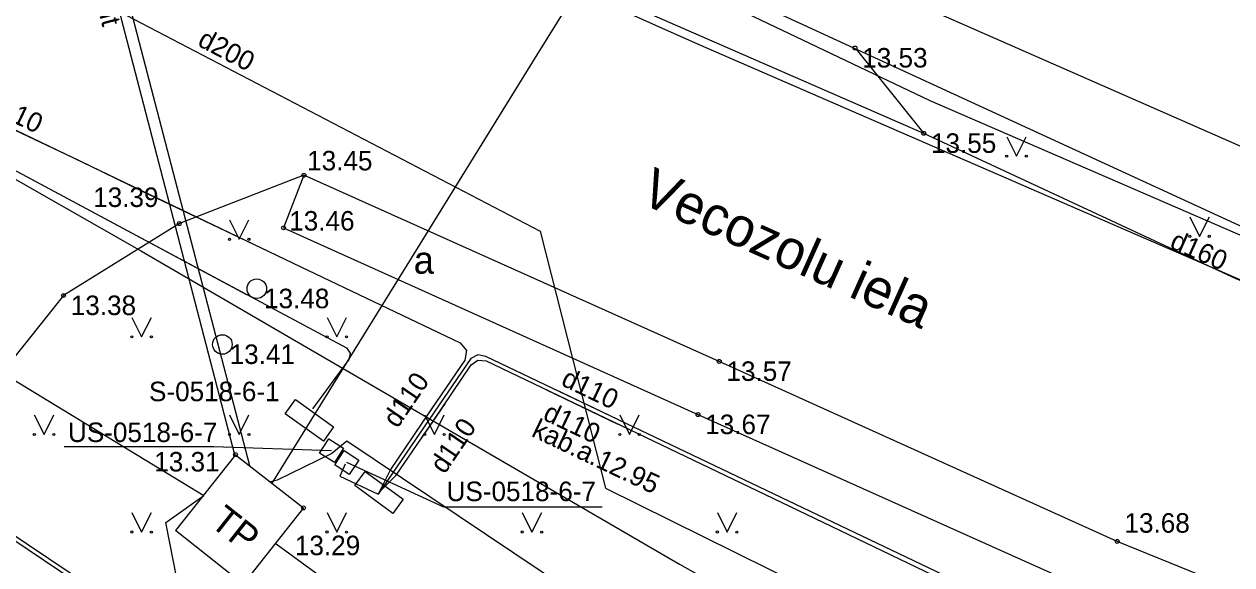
# Model space of a CAD drawing. Extents: x 503904 to 504094, y 304688 to 304960.
# Drawn here: x 503996.99 to 504027.93, y 304884.16 to 304898.01 of the extents above; entities that cross this region are included whole.
import ezdxf

# ---------------------------------------------------------------- set-up
doc = ezdxf.new("R2010")
doc.units = 0
for name, color, linetype in [('APGR_SARK_####_####_#', 7, 'Continuous'), ('APGS_ACRL_####_####_#', 7, 'Continuous'), ('APGS_ACRL_####_TKST_#', 7, 'Continuous'), ('APGS_ELEM_####_####_#', 7, 'Continuous'), ('APGS_VADP_ZSPR_####_#', 7, 'Continuous'), ('APGS_VADP_ZSPR_TKST_#', 7, 'Continuous'), ('BUVE_ELEM_####_####_#', 7, 'Continuous'), ('CELI_CAPM_####_####_#', 7, 'Continuous'), ('CELI_CMAL_####_####_#', 7, 'Continuous'), ('CELI_CSEG_####_TKST_#', 7, 'Continuous'), ('CELI_IELA_####_TKST_#', 7, 'Continuous'), ('CELI_TAKA_####_####_#', 7, 'Continuous'), ('ELEK_ACRL_####_####_#', 7, 'Continuous'), ('ELEK_ELEM_####_####_#', 7, 'Continuous'), ('ELEK_ELEM_####_TKST_#', 7, 'Continuous'), ('ELEK_STTP_####_####_#', 7, 'Continuous'), ('ELEK_STTP_####_TKST_#', 7, 'Continuous'), ('ELEK_VADP_VSPR_####_#', 7, 'Continuous'), ('ELEK_VADP_ZSPR_####_#', 7, 'Continuous'), ('ELEK_VADP_ZSPR_TKST_#', 7, 'Continuous'), ('ELEK_VADV_VSPR_####_#', 7, 'Continuous'), ('ELEK_VADV_ZSPR_####_#', 7, 'Continuous'), ('GAZE_VADP_VSP2_####_#', 7, 'Continuous'), ('GAZE_VADP_VSP2_TKST_#', 7, 'Continuous'), ('RAMI_UZMR_####_####_#', 7, 'Continuous'), ('RELJ_AATZ_####_TKST_#', 7, 'Continuous'), ('RELJ_ELEM_####_####_#', 7, 'Continuous'), ('ROBZ_UZMR_####_####_#', 7, 'Continuous'), ('SAKK_KKAN_####_####_#', 7, 'Continuous'), ('TERT_ELEM_####_####_#', 7, 'Continuous'), ('UDTK_VADP_UDEN_####_#', 7, 'Continuous'), ('UDTK_VADP_UDEN_TKST_#', 7, 'Continuous')]:
    doc.layers.add(name, color=color, linetype=linetype)

msp = doc.modelspace()

# ---------------------------------------------------------------- linework, layer by layer
at = {"layer": 'APGR_SARK_####_####_#'}
msp.add_line((503977.453, 304917.18), (504048.875, 304885.773), dxfattribs=at)
at = {"layer": 'APGS_ACRL_####_####_#'}
for points in [[(503997.708, 304905.8), (503994.46, 304899.393), (503993.378, 304897.257), (503993.361, 304897.025), (503993.516, 304896.851), (503996.758, 304895.298), (503998.379, 304894.525), (504000, 304893.745), (504003.241, 304892.193)], [(504010.375, 304888.642), (504012.204, 304887.766)], [(504012.399, 304887.79), (504010.595, 304888.651)], [(504006.987, 304887.503), (504007.597, 304888.4)], [(504007.766, 304888.284), (504007.156, 304887.387)]]:
    msp.add_lwpolyline(points, dxfattribs=at)
at = {"layer": 'APGS_ELEM_####_####_#'}
msp.add_lwpolyline([(504005.73, 304886.552), (504006.698, 304885.843), (504006.432, 304885.48), (504005.464, 304886.189)], close=True, dxfattribs=at)
at = {"layer": 'APGS_VADP_ZSPR_####_#'}
for points in [[(503994.396, 304908.162), (503998.01, 304906.396), (503995.543, 304901.529), (503993.378, 304897.257), (503993.361, 304897.025), (503993.516, 304896.85), (503996.758, 304895.3), (504000, 304893.749), (504004.081, 304891.797), (504008.162, 304889.845), (504008.322, 304889.653), (504008.281, 304889.406), (504007.328, 304888.005), (504006.375, 304886.604), (504006.058, 304885.968)], [(504034.948, 304837.203), (504032.464, 304838.354), (504032.46, 304838.624), (504032.497, 304838.963), (504034.767, 304843.029), (504037.037, 304847.095), (504041.785, 304855.598), (504046.532, 304864.101), (504046.909, 304866.055), (504048.051, 304868.025), (504049.192, 304869.995), (504049.205, 304870.202), (504049.157, 304870.343), (504042.295, 304873.577), (504035.433, 304876.812), (504031.898, 304878.478), (504020.359, 304883.989), (504008.82, 304889.499), (504008.617, 304889.54), (504008.431, 304889.443), (504006.058, 304885.968)], [(504006.081, 304886.016), (504006.524, 304886.457), (504007.485, 304887.87), (504008.446, 304889.284), (504008.616, 304889.405), (504008.824, 304889.386), (504016.168, 304885.866), (504023.512, 304882.345), (504029.465, 304879.528), (504035.491, 304876.677), (504037.943, 304875.532), (504038.212, 304875.634), (504038.416, 304876.08), (504038.226, 304875.558), (504038.331, 304875.343), (504039.638, 304874.712), (504041.796, 304873.674), (504045.914, 304871.662), (504049.181, 304870.056), (504051.511, 304869.798), (504052.144, 304869.735)], [(504005.217, 304886.74), (504005.076, 304886.431), (504006.058, 304885.968)]]:
    msp.add_lwpolyline(points, dxfattribs=at)
at = {"layer": 'BUVE_ELEM_####_####_#'}
for centre in [(504002.95, 304891.234), (504002.069, 304889.806)]:
    msp.add_circle(centre, 0.25, dxfattribs=at)
at = {"layer": 'CELI_CAPM_####_####_#'}
msp.add_lwpolyline([(504042.469, 304879.012), (504039.999, 304879.481), (504033.709, 304881.219), (504024.994, 304884.76), (504014.798, 304889.372), (504004.157, 304894.141)], dxfattribs=at)
at = {"layer": 'CELI_CMAL_####_####_#'}
for points in [[(504056.369, 304885.722), (504054.86, 304884.787), (504047.246, 304885.659), (504038.184, 304887.536), (504028.058, 304891.478), (504020.037, 304895.213), (504011.327, 304899.02)], [(504004.157, 304894.141), (504000.966, 304892.903), (503997.999, 304891.059), (503994.598, 304886.807), (503991.776, 304882.213), (503990.847, 304877.876)], [(504004.157, 304894.141), (504003.635, 304892.793), (504014.253, 304888.009), (504024.188, 304883.551), (504033.132, 304879.868), (504039.457, 304878.088), (504042.126, 304877.631), (504042.469, 304879.012)]]:
    msp.add_lwpolyline(points, dxfattribs=at)
at = {"layer": 'CELI_TAKA_####_####_#'}
msp.add_lwpolyline([(504018.302, 304897.367), (504020.037, 304895.213)], dxfattribs=at)
at = {"layer": 'ELEK_ACRL_####_####_#'}
msp.add_lwpolyline([(503986.232, 304899.912), (504002.69, 304891.089)], dxfattribs=at)
at = {"layer": 'ELEK_ELEM_####_####_#'}
for points in [[(504003.942, 304888.393), (504004.919, 304887.698), (504004.658, 304887.331), (504003.681, 304888.026)], [(504004.938, 304886.781), (504004.561, 304887.019), (504004.796, 304887.391), (504005.173, 304887.153)], [(504005.317, 304886.477), (504004.946, 304886.725), (504005.191, 304887.091), (504005.562, 304886.843)]]:
    msp.add_lwpolyline(points, close=True, dxfattribs=at)
at = {"layer": 'ELEK_ELEM_####_TKST_#'}
for points in [[(503998.012, 304887.191), (504001.849, 304887.191), (504004.867, 304887.086)], [(504011.796, 304885.637), (504007.738, 304885.637), (504005.254, 304886.784)]]:
    msp.add_lwpolyline(points, dxfattribs=at)
at = {"layer": 'ELEK_STTP_####_####_#'}
for points in [[(504002.404, 304886.982), (504004.147, 304885.62), (504002.601, 304883.668), (504000.867, 304885.041)], [(504002.404, 304886.982), (504000.867, 304885.041)]]:
    msp.add_lwpolyline(points, dxfattribs=at)
at = {"layer": 'ELEK_VADP_VSPR_####_#'}
msp.add_line((503999.944, 304882.63), (503993.832, 304886.735), dxfattribs=at)
msp.add_lwpolyline([(504017.859, 304874.234), (504017.356, 304874.141), (504010.022, 304879.253), (504006.684, 304878.224), (503993.887, 304886.818), (503989.112, 304889.931), (503981.666, 304895.299)], dxfattribs=at)
at = {"layer": 'ELEK_VADP_ZSPR_####_#'}
for points in [[(503997.15, 304907.1), (503997.915, 304904.16), (504000, 304896.148), (504001.196, 304891.552), (504002.392, 304886.957)], [(504002.77, 304886.696), (504000, 304897.339), (503998.067, 304904.766), (503997.502, 304906.938)], [(504012.009, 304900.262), (504010.129, 304897.225), (504006.795, 304891.841)], [(503986.232, 304899.912), (504000, 304892.531), (504005.246, 304889.719), (504005.346, 304889.587), (504005.312, 304889.424), (504004.381, 304888.161)], [(504006.795, 304891.841), (504003.461, 304886.457), (504003.335, 304886.254)], [(504022.559, 304867.983), (504026.163, 304873.33), (504016.676, 304879.682), (504010.965, 304883.506), (504005.254, 304887.33), (504004.874, 304887.016), (504003.476, 304886.332), (504003.299, 304886.283)], [(504000.416, 304838.443), (503998.481, 304840.029), (503998.306, 304845.209), (503998.373, 304849.851), (503998.508, 304857.812), (503999.848, 304869.157), (504000.657, 304875.395), (504001.302, 304879.043), (504001.471, 304880.898), (504000.618, 304885.243), (504001.595, 304885.938)]]:
    msp.add_lwpolyline(points, dxfattribs=at)
at = {"layer": 'ELEK_VADV_VSPR_####_#'}
msp.add_line((504003.444, 304884.699), (504017.859, 304874.234), dxfattribs=at)
at = {"layer": 'ELEK_VADV_ZSPR_####_#'}
msp.add_line((503983.376, 304897.026), (504001.595, 304885.938), dxfattribs=at)
at = {"layer": 'GAZE_VADP_VSP2_####_#'}
msp.add_lwpolyline([(503989.698, 304903.414), (504000, 304898.037), (504010.212, 304892.707), (504011.048, 304889.414), (504011.884, 304886.121), (504025.295, 304879.492), (504038.706, 304872.862), (504042.754, 304870.726), (504047.158, 304868.745), (504052.063, 304869.587)], dxfattribs=at)
at = {"layer": 'RAMI_UZMR_####_####_#'}
msp.add_lwpolyline([(503923.253, 304801.015), (503981.982, 304759.672), (503995.48, 304748.813), (504027.75, 304817.255), (504060.02, 304885.696), (504048.875, 304885.773), (504036.803, 304888.853), (503994.536, 304908.303), (503981.123, 304894.75), (503978.518, 304892.436), (503950.886, 304846.726), (503923.253, 304801.015)], dxfattribs=at)
at = {"layer": 'RELJ_ELEM_####_####_#'}
for centre in [(504018.276, 304897.399), (504020.037, 304895.213), (504004.157, 304894.141), (504000.966, 304892.903), (504003.635, 304892.793), (503997.999, 304891.059), (504014.798, 304889.372), (504014.253, 304888.009), (504002.404, 304886.982), (504004.147, 304885.62), (504024.994, 304884.76)]:
    msp.add_circle(centre, 0.05, dxfattribs=at)
at = {"layer": 'ROBZ_UZMR_####_####_#'}
msp.add_lwpolyline([(503976.959, 304916.696), (503989.759, 304910.584), (503994.536, 304908.303), (504011.531, 304900.187), (504020.191, 304896.051), (504036.803, 304888.853), (504048.875, 304885.773), (504074.124, 304885.169)], dxfattribs=at)
at = {"layer": 'SAKK_KKAN_####_####_#'}
msp.add_lwpolyline([(503986.316, 304899.997), (504000, 304892.196), (504013.782, 304884.178), (504021.554, 304879.802), (504033.218, 304873.459), (504039.007, 304870.064), (504043.395, 304867.859), (504047.782, 304865.655), (504048.401, 304866.822), (504050.758, 304867.21)], dxfattribs=at)
at = {"layer": 'TERT_ELEM_####_####_#'}
for p, q in [((504022.164, 304895.128), (504022.414, 304894.628)), ((504022.414, 304894.628), (504022.664, 304895.128)), ((504002.25, 304893), (504002.5, 304892.5)), ((504002.5, 304892.5), (504002.75, 304893)), ((504026.854, 304893.075), (504027.104, 304892.575)), ((504027.104, 304892.575), (504027.354, 304893.075)), ((503999.75, 304890.5), (504000, 304890)), ((504000, 304890), (504000.25, 304890.5)), ((504004.75, 304890.5), (504005, 304890)), ((504005, 304890), (504005.25, 304890.5)), ((503997.25, 304888), (503997.5, 304887.5)), ((503997.5, 304887.5), (503997.75, 304888)), ((504002.25, 304888), (504002.5, 304887.5)), ((504002.5, 304887.5), (504002.75, 304888)), ((504007.25, 304888), (504007.5, 304887.5)), ((504007.5, 304887.5), (504007.75, 304888)), ((504012.25, 304888), (504012.5, 304887.5)), ((504012.5, 304887.5), (504012.75, 304888)), ((503999.75, 304885.5), (504000, 304885)), ((504000, 304885), (504000.25, 304885.5)), ((504004.75, 304885.5), (504005, 304885)), ((504005, 304885), (504005.25, 304885.5)), ((504009.75, 304885.5), (504010, 304885)), ((504010, 304885), (504010.25, 304885.5)), ((504014.75, 304885.5), (504015, 304885)), ((504015, 304885), (504015.25, 304885.5))]:
    msp.add_line(p, q, dxfattribs=at)
for centre, radius in [((504022.164, 304894.628), 0.028), ((504022.664, 304894.628), 0.0263), ((504002.25, 304892.5), 0.028), ((504002.75, 304892.5), 0.0263), ((504026.853, 304892.575), 0.028), ((504027.353, 304892.575), 0.0263), ((503999.75, 304890), 0.028), ((504000.25, 304890), 0.0263), ((504004.75, 304890), 0.028), ((504005.25, 304890), 0.0263), ((503997.25, 304887.5), 0.028), ((503997.75, 304887.5), 0.0263), ((504002.25, 304887.5), 0.028), ((504002.75, 304887.5), 0.0263), ((504007.25, 304887.5), 0.028), ((504007.75, 304887.5), 0.0263), ((504012.25, 304887.5), 0.028), ((504012.75, 304887.5), 0.0263), ((503999.75, 304885), 0.028), ((504000.25, 304885), 0.0263), ((504004.75, 304885), 0.028), ((504005.25, 304885), 0.0263), ((504009.75, 304885), 0.028), ((504010.25, 304885), 0.0263), ((504014.75, 304885), 0.028), ((504015.25, 304885), 0.0263)]:
    msp.add_circle(centre, radius, dxfattribs=at)
at = {"layer": 'UDTK_VADP_UDEN_####_#'}
msp.add_lwpolyline([(504059.328, 304884.23), (504052.534, 304884.693), (504043.033, 304885.34), (504032.956, 304889.369), (504014.268, 304897.491), (504000, 304903.846), (503993.127, 304906.879)], dxfattribs=at)

# ---------------------------------------------------------------- texts
at = {"layer": 'APGS_ACRL_####_TKST_#'}
for rotation, p in [(334.405, (503995.971, 304895.841)), (55.7903, (504006.555, 304887.638)), (334.388, (504010.717, 304888.774)), (334.4861, (504010.251, 304887.894)), (55.7893, (504007.762, 304886.464))]:
    msp.add_text('d110', height=0.5, rotation=rotation, dxfattribs=at).set_placement(p)
at = {"layer": 'APGS_VADP_ZSPR_TKST_#'}
msp.add_text('kab.a.12.95', height=0.5, rotation=334.4861, dxfattribs=at).set_placement((504009.96, 304887.468))
at = {"layer": 'CELI_CSEG_####_TKST_#'}
msp.add_text('a', height=0.7, dxfattribs=at).set_placement((504006.97, 304891.618))
at = {"layer": 'CELI_IELA_####_TKST_#'}
msp.add_text('Vecozolu iela', height=1, rotation=335.8594, dxfattribs=at).set_placement((504012.724, 304893.449))
at = {"layer": 'ELEK_ELEM_####_TKST_#'}
for s, p in [('S-0518-6-1', (504000.189, 304888.352)), ('US-0518-6-7', (503998.113, 304887.306)), ('US-0518-6-7', (504007.812, 304885.793))]:
    msp.add_text(s, height=0.5, dxfattribs=at).set_placement(p)
at = {"layer": 'ELEK_STTP_####_TKST_#'}
msp.add_text('TP', height=0.7, rotation=321.6205, dxfattribs=at).set_placement((504001.719, 304885.184))
at = {"layer": 'ELEK_VADP_ZSPR_TKST_#'}
msp.add_text('orient', height=0.5, rotation=284.5879, dxfattribs=at).set_placement((503998.578, 304899.542))
at = {"layer": 'GAZE_VADP_VSP2_TKST_#'}
msp.add_text('d200', height=0.5, rotation=332.4407, dxfattribs=at).set_placement((504001.405, 304897.473))
at = {"layer": 'RELJ_AATZ_####_TKST_#'}
for s, p in [(' 13.53', (504018.276, 304896.899)), (' 13.55', (504020.037, 304894.713)), (' 13.45', (504004.055, 304894.264)), (' 13.39', (503998.573, 304893.327)), (' 13.46', (504003.596, 304892.723)), (' 13.48', (504002.95, 304890.734)), (' 13.38', (503997.999, 304890.559)), (' 13.41', (504002.069, 304889.306)), (' 13.57', (504014.798, 304888.872)), (' 13.67', (504014.253, 304887.509)), (' 13.31', (504000.138, 304886.552)), (' 13.68', (504024.994, 304884.984)), (' 13.29', (504003.741, 304884.408))]:
    msp.add_text(s, height=0.5, dxfattribs=at).set_placement(p)
at = {"layer": 'UDTK_VADP_UDEN_TKST_#'}
msp.add_text('d160', height=0.5, rotation=335.9922, dxfattribs=at).set_placement((504026.312, 304892.291))

doc.saveas('drawing.dxf')
